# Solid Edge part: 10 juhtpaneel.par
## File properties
Author: Henri
Template: Normal.par
Last saved by: Henri
Revision: 8
Application: Solid Edge
Accuracy: 0,990
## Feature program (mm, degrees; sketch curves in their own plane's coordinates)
sketch for "unnamed Protrusion 1" plane through (0, 0, 0) normal (0, 0, 1) x-axis (1, 0, 0)
  line (-20, -175) -> (-20, 175)
  line (-20, 175) -> (20, 175)
  line (20, 175) -> (20, -175)
  line (20, -175) -> (-20, -175)
extrude "unnamed Protrusion 1" add finite 40 along +normal
sketch for "ExtrudedProtrusion_2" plane through (0, 0, 0) normal (0, 0, 1) x-axis (1, 0, 0)
  line (-95, 62.5) -> (-20, 62.5)
  line (-20, 62.5) -> (-20, 112.5)
  line (-20, 112.5) -> (-95, 112.5)
  line (-95, 112.5) -> (-95, 62.5)
extrude "ExtrudedProtrusion_2" add finite 2.5 along +normal
sketch for "ExtrudedProtrusion_3" plane through (0, 0, 0) normal (0, 0, 1) x-axis (1, 0, 0)
  line (-35, 77.5) -> (-15, 77.5)
  line (-15, 97.5) -> (-15, 77.5)
  line (-35, 97.5) -> (-15, 97.5)
  line (-35, 97.5) -> (-35, 77.5)
extrude "ExtrudedProtrusion_3" add finite 60 along +normal
sketch for "ExtrudedProtrusion_4" plane through (-35, 87.5, 31.25) normal (-1, 0, 0) x-axis (0, -1, 0)
  circle centre (0, 21.25) radius 2.5
extrude "ExtrudedProtrusion_4" add finite 7.5 along +normal
sketch for "unnamed RevolvedProtrusion 1" plane through (-27.5, 87.5, 52.5) normal (0, 0, 1) x-axis (1, 0, 0)
  line (-14.5, 24) -> (-14.5, 18.25)
  line (-15, 17.75) -> (-14.5, 18.25)
  line (-15, 17.75) -> (-15, 14.75)
  line (-15, 14.75) -> (-14.5, 13.5427)
  line (-14.5, 13.5427) -> (-14.5, 0)
  line (-13.75, 0) -> (-14.5, 0)
  line (-13.75, 26.25) -> (-13.75, 0)
revolve "unnamed RevolvedProtrusion 1" add finite 360 deg
sketch for "unnamed RevolvedProtrusion 2" plane through (-27.5, 87.5, 52.5) normal (0, 0, 1) x-axis (1, 0, 0)
  circle centre (-13.75, 16.25) radius 1
revolve "unnamed RevolvedProtrusion 2" add finite 360 deg
pattern "Pattern_1" of "unnamed RevolvedProtrusion 1" along a curve  XDirCount = 9; XDirSpacing = 50 mm
revolve "unnamed RevolvedProtrusion 3" add finite 360 deg
revolve "unnamed RevolvedProtrusion 4" add finite 360 deg
revolve "unnamed RevolvedProtrusion 5" add finite 360 deg
revolve "unnamed RevolvedProtrusion 6" add finite 360 deg
revolve "unnamed RevolvedProtrusion 7" add finite 360 deg
revolve "unnamed RevolvedProtrusion 8" add finite 360 deg
revolve "unnamed RevolvedProtrusion 9" add finite 360 deg
revolve "unnamed RevolvedProtrusion 10" add finite 360 deg
fillet "Round_1" radius 1.5
sketch used by "ExtrudedProtrusion_6" plane through (0.75, 0, 40) normal (0, 0, 1) x-axis (0, 1, 0)
extrude "ExtrudedProtrusion_6" add finite 7.5 along +normal
sketch used by "unnamed Cutout 1" plane through (-0.6086, 106.7159, 43.75) normal (0.371391, -0.928477, 0) x-axis (0.928477, 0.371391, 0)
extrude "unnamed Cutout 1" cut through along -normal
sketch used by "unnamed Cutout 2" plane through (-8.0348, 49.7139, 43.75) normal (-0.371391, -0.928477, 0) x-axis (0.928477, -0.371391, 0)
extrude "unnamed Cutout 2" cut through along -normal
sketch for "unnamed Cutout 3" plane through (-4.3225, 116.0007, 44.7494) normal (-0.319569, -0.127827, 0.938901) x-axis (0.871748, 0.348699, 0.344186)
extrude "unnamed Cutout 3" cut finite 0.5 along -normal
sketch for "ExtrudedProtrusion_7" #1 plane through (-4.3225, 116.0007, 44.7494) normal (-0.319569, -0.127827, 0.938901) x-axis (0.871748, 0.348699, 0.344186)
  line (-6.7381, 8.75) -> (6.7381, 8.75)
  line (6.7381, 8.75) -> (6.7381, -8.75)
  line (-6.7381, -8.75) -> (6.7381, -8.75)
  line (-6.7381, 8.75) -> (-6.7381, -8.75)
sketch for "ExtrudedProtrusion_7" #2 plane through (-4.3225, 116.0007, 44.7494) normal (-0.319569, -0.127827, 0.938901) x-axis (0.871748, 0.348699, 0.344186)
sketch for "ExtrudedProtrusion_7" #3 plane through (-4.3225, 116.0007, 44.7494) normal (-0.319569, -0.127827, 0.938901) x-axis (0.871748, 0.348699, 0.344186)
  circle centre (-7.4881, 7.6034) radius 0.25
sketch for "ExtrudedProtrusion_7" #4 plane through (-4.3225, 116.0007, 44.7494) normal (-0.319569, -0.127827, 0.938901) x-axis (0.871748, 0.348699, 0.344186)
  circle centre (-7.4881, 6.7282) radius 0.25
sketch for "ExtrudedProtrusion_7" #5 plane through (-4.3225, 116.0007, 44.7494) normal (-0.319569, -0.127827, 0.938901) x-axis (0.871748, 0.348699, 0.344186)
  circle centre (-7.4881, 5.9624) radius 0.25
sketch for "ExtrudedProtrusion_7" #6 plane through (-4.3225, 116.0007, 44.7494) normal (-0.319569, -0.127827, 0.938901) x-axis (0.871748, 0.348699, 0.344186)
  circle centre (-7.4881, 4.4308) radius 0.25
sketch for "ExtrudedProtrusion_7" #7 plane through (-4.3225, 116.0007, 44.7494) normal (-0.319569, -0.127827, 0.938901) x-axis (0.871748, 0.348699, 0.344186)
  circle centre (-7.4881, 3.7014) radius 0.25
extrude "ExtrudedProtrusion_7" add finite 0.5 along +normal
fillet "Round_2" radius 0.2
sketch for "ExtrudedCutout_4" plane through (-4.3209, 58.9987, 44.75) normal (-0.319565, 0.127826, 0.938903) x-axis (0.871749, -0.3487, 0.344182)
extrude "ExtrudedCutout_4" cut finite 0.5 along -normal
sketch for "ExtrudedProtrusion_8" #1 plane through (-4.3209, 58.9987, 44.75) normal (-0.319565, 0.127826, 0.938903) x-axis (0.871749, -0.3487, 0.344182)
sketch for "ExtrudedProtrusion_8" #2 plane through (-4.3209, 58.9987, 44.75) normal (-0.319565, 0.127826, 0.938903) x-axis (0.871749, -0.3487, 0.344182)
  circle centre (-7.3671, -2.1335) radius 0.25
sketch for "ExtrudedProtrusion_8" #3 plane through (-4.3209, 58.9987, 44.75) normal (-0.319565, 0.127826, 0.938903) x-axis (0.871749, -0.3487, 0.344182)
  circle centre (-7.3671, -1.3677) radius 0.25
sketch for "ExtrudedProtrusion_8" #4 plane through (-4.3209, 58.9987, 44.75) normal (-0.319565, 0.127826, 0.938903) x-axis (0.871749, -0.3487, 0.344182)
  circle centre (-7.3671, 7.203) radius 0.25
extrude "ExtrudedProtrusion_8" add finite 0.5 along +normal
fillet "Round_3" radius 0.2
sketch used by "ExtrudedProtrusion_9" plane through (0, 87.5, 0) normal (0, -1, 0) x-axis (1, 0, 0)
  line (-57.5, 37.5) -> (-73.3744, 37.5)
  line (-55, 35) -> (-55, 30)
  line (-85, 27.5) -> (-57.5, 27.5)
  arc centre (-85, 32.5) radius 5 from (-90, 32.5) to (-85, 27.5) ccw
  arc centre (-57.5, 35) radius 2.5 from (-57.5, 37.5) to (-55, 35) cw
  arc centre (-57.5, 30) radius 2.5 from (-57.5, 27.5) to (-55, 30) ccw
  line (-90, 32.5) -> (-99.1666, 68.1143)
  line (-96.7455, 71.2375) -> (-91.5997, 71.2375)
  line (-89.3147, 69.7516) -> (-75.6595, 38.9858)
  arc centre (-96.7455, 68.7375) radius 2.5 from (-99.1666, 68.1143) to (-96.7455, 71.2375) cw
  arc centre (-91.5997, 68.7375) radius 2.5 from (-91.5997, 71.2375) to (-89.3147, 69.7516) cw
  arc centre (-73.3744, 40) radius 2.5 from (-75.6595, 38.9858) to (-73.3744, 37.5) ccw
extrude "ExtrudedProtrusion_9" add finite 35 symmetric
sketch for "unnamed Protrusion 2" plane through (0, 87.5, 0) normal (0, -1, 0) x-axis (1, 0, 0)
  line (-48.5, 12.5) -> (-35, 12.5)
  line (-35, 12.5) -> (-35, 7.5)
  line (-35, 7.5) -> (-48.5, 7.5)
  arc centre (-48.5, 9) radius 1.5 from (-50, 9) to (-48.5, 7.5) ccw
  line (-50, 11) -> (-50, 9)
  arc centre (-48.5, 11) radius 1.5 from (-50, 11) to (-48.5, 12.5) cw
extrude "unnamed Protrusion 2" add finite 30 symmetric
sketch for "unnamed RevolvedProtrusion 11" plane through (0, 87.5, 0) normal (0, -1, 0) x-axis (1, 0, 0)
revolve "unnamed RevolvedProtrusion 11" add finite 360 deg
fillet "Round_6" radius 2
sketch for "ExtrudedCutout_7" plane through (0, 87.5, 0) normal (0, -1, 0) x-axis (1, 0, 0)
  line (-89.3147, 69.7516) -> (-75.6595, 38.9858)
  arc centre (-73.3744, 40) radius 2.5 from (-75.6595, 38.9858) to (-73.3744, 37.5) ccw
  line (-73.3744, 37.5) -> (-57.5, 37.5)
  line (-57.5, 37.5) -> (-73.3744, 35)
  arc centre (-73.3744, 40) radius 5 from (-77.9445, 37.9716) to (-73.3744, 35) ccw
  line (-92.7093, 71.2375) -> (-77.9445, 37.9716)
  line (-92.7093, 71.2375) -> (-91.5997, 71.2375)
  arc centre (-91.5997, 68.7375) radius 2.5 from (-91.5997, 71.2375) to (-89.3147, 69.7516) cw
extrude "ExtrudedCutout_7" cut finite 25 symmetric
fillet "Round_7" radius 2.5
fillet "Round_8" radius 1
fillet "Round_10" radius 2
sketch for "unnamed Cutout 4" plane through (0.75, 0, 40) normal (0, 0, 1) x-axis (0, 1, 0)
  line (-175, -19.25) -> (0, -19.25)
  line (0, 21.0459) -> (0, -19.25)
  line (-175, 21.0459) -> (0, 21.0459)
  line (-175, 21.0459) -> (-175, -19.25)
extrude "unnamed Cutout 4" cut through along -normal
sketch for "ExtrudedProtrusion_13" plane through (0, 87.5, 0) normal (0, -1, 0) x-axis (1, 0, 0)
  line (-33.5, 60) -> (-16.5, 60)
  line (-33.5, 70) -> (-16.5, 60)
  line (-33.5, 70) -> (-33.5, 60)
extrude "ExtrudedProtrusion_13" add finite 17 symmetric
sketch for "ExtrudedCutout_10" plane through (-33.5, 87.5, 65) normal (-1, 0, 0) x-axis (0, -1, 0)
  line (7.75, 4.25) -> (-7.75, 4.25)
  line (-7.75, -4.25) -> (-7.75, 4.25)
  line (7.75, -4.25) -> (-7.75, -4.25)
  line (7.75, 4.25) -> (7.75, -4.25)
extrude "ExtrudedCutout_10" cut finite 0.25 along -normal
fillet "Round_11" radius 0.25
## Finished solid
Body 1: solid body, 275 faces, 506 edges, 230 vertices.
  Faces by surface: cylinder 113, plane 79, torus 35, sphere 24, cone 20, blend 4
  Edges by curve: line 232, circle 197, intersection 39, ellipse 38
Bounding box of the edges (mm; curved faces can reach further): 119.246 x 175.000 x 76.266, from (-99.2455, 0, 0) to (20, 175, 76.2657).
Cylindrical faces by radius (mm): R0.2 x8, R0.25 x16, R0.75 x18, R1 x7, R1.25 x9, R1.5 x19, R2 x11, R2.5 x22, R5 x2, R10 x1
Conical faces (half-angle, radius in mm at the cone's reference point): 22.4965 deg R1.25 x9, 45 deg R0.75 x9, 45 deg R2.5 x1, 45 deg R7.5 x1
Toroidal faces (ring radius, tube radius in mm): R0.05 r0.2 x11, R1.5 r1 x2, R2.5 r2.5 x2, R3 r1.5 x6, R3.5 r1 x2, R5 r2.5 x2, R8.5 r1.5 x1, R16.25 r1 x9
Spherical faces by radius (mm): R0.25 x2, R1.25 x9, R1.5 x4, R2.5 x8, R3.75 x1
Planar faces by outward normal: +x 5, +y 8, +z 8, -x 9, -y 8, -z 4, oblique 37
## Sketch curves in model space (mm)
line (-33.5, 79.75, 69.25) -> (-33.5, 95.25, 69.25)
line (-33.5, 79.75, 69.25) -> (-33.5, 79.75, 60.75)
line (-33.5, 79.75, 60.75) -> (-33.5, 95.25, 60.75)
line (-33.5, 95.25, 60.75) -> (-33.5, 95.25, 69.25)
line (20, -175, 40) -> (20, 0, 40)
line (-20.2959, -175, 40) -> (20, -175, 40)
line (-20.2959, -175, 40) -> (-20.2959, 0, 40)
line (-20.2959, 0, 40) -> (20, 0, 40)
arc centre (-73.3744, 87.5, 40) radius 5 from (-77.9445, 87.5, 37.9716) through (-76.1, 87.5, 35.8082) to (-73.3744, 87.5, 35)
line (-57.5, 87.5, 37.5) -> (-73.3744, 87.5, 35)
line (-73.3744, 87.5, 37.5) -> (-57.5, 87.5, 37.5)
arc centre (-73.3744, 87.5, 40) radius 2.5 from (-75.6595, 87.5, 38.9858) through (-74.7372, 87.5, 37.9041) to (-73.3744, 87.5, 37.5)
line (-89.3147, 87.5, 69.7516) -> (-75.6595, 87.5, 38.9858)
arc centre (-91.5997, 87.5, 68.7375) radius 2.5 from (-91.5997, 87.5, 71.2375) through (-90.2369, 87.5, 70.8333) to (-89.3147, 87.5, 69.7516)
line (-92.7093, 87.5, 71.2375) -> (-91.5997, 87.5, 71.2375)
line (-92.7093, 87.5, 71.2375) -> (-77.9445, 87.5, 37.9716)
circle centre (-44, 87.5, 52.5) radius 16.25
arc centre (-73.3744, 87.5, 40) radius 2.5 from (-75.6595, 87.5, 38.9858) through (-74.7372, 87.5, 37.9041) to (-73.3744, 87.5, 37.5)
line (-89.3147, 87.5, 69.7516) -> (-75.6595, 87.5, 38.9858)
arc centre (-91.5997, 87.5, 68.7375) radius 2.5 from (-91.5997, 87.5, 71.2375) through (-90.2369, 87.5, 70.8333) to (-89.3147, 87.5, 69.7516)
line (-96.7455, 87.5, 71.2375) -> (-91.5997, 87.5, 71.2375)
arc centre (-96.7455, 87.5, 68.7375) radius 2.5 from (-99.1666, 87.5, 68.1143) through (-98.6755, 87.5, 70.3266) to (-96.7455, 87.5, 71.2375)
line (-90, 87.5, 32.5) -> (-99.1666, 87.5, 68.1143)
arc centre (-85, 87.5, 32.5) radius 5 from (-90, 87.5, 32.5) through (-88.4312, 87.5, 28.8631) to (-85, 87.5, 27.5)
line (-85, 87.5, 27.5) -> (-57.5, 87.5, 27.5)
arc centre (-57.5, 87.5, 30) radius 2.5 from (-57.5, 87.5, 27.5) through (-55.6816, 87.5, 28.2844) to (-55, 87.5, 30)
line (-55, 87.5, 35) -> (-55, 87.5, 30)
arc centre (-57.5, 87.5, 35) radius 2.5 from (-57.5, 87.5, 37.5) through (-55.6816, 87.5, 36.7156) to (-55, 87.5, 35)
line (-57.5, 87.5, 37.5) -> (-73.3744, 87.5, 37.5)
circle centre (-41.25, 103.75, 52.5) radius 1
line (-42.4017, 87.5, 52.5) -> (-39.1797, 87.5, 52.5)
line (-7.5722, 103.9305, 47.5) -> (6.3581, 109.5026, 47.5)
line (-7.5722, 103.9305, 47.5) -> (-7.5722, 103.9305, 42)
line (-7.5722, 103.9305, 42) -> (6.3581, 109.5026, 47.5)
line (-15, 52.5, 42) -> (-1.0695, 46.9278, 47.5)
line (-15, 52.5, 47.5) -> (-15, 52.5, 42)
line (-15, 52.5, 47.5) -> (-1.0695, 46.9278, 47.5)
arc centre (-48.5, 87.5, 9) radius 1.5 from (-50, 87.5, 9) through (-49.5294, 87.5, 7.9089) to (-48.5, 87.5, 7.5)
line (-50, 87.5, 11) -> (-50, 87.5, 9)
arc centre (-48.5, 87.5, 11) radius 1.5 from (-50, 87.5, 11) through (-49.5294, 87.5, 12.0911) to (-48.5, 87.5, 12.5)
line (-48.5, 87.5, 12.5) -> (-35, 87.5, 12.5)
line (-35, 87.5, 12.5) -> (-35, 87.5, 7.5)
line (-35, 87.5, 7.5) -> (-48.5, 87.5, 7.5)
arc centre (-75, 87.5, 17.5) radius 3.75 from (-77.5, 87.5, 14.7049) through (-78.7484, 87.5, 17.6087) to (-77.5, 87.5, 20.2951)
arc centre (-75, 87.5, 17.5) radius 3.75 from (-77.5, 87.5, 14.7049) through (-78.7484, 87.5, 17.6087) to (-77.5, 87.5, 20.2951)
line (-77.5, 87.5, 12.5) -> (-77.5, 87.5, 14.7049)
line (-77.5, 87.5, 12.5) -> (-82.5, 87.5, 7.5)
line (-83.5, 87.5, 7.5) -> (-82.5, 87.5, 7.5)
arc centre (-83.5, 87.5, 6) radius 1.5 from (-85, 87.5, 6) through (-84.5294, 87.5, 7.0911) to (-83.5, 87.5, 7.5)
line (-85, 87.5, 2.5) -> (-85, 87.5, 6)
line (-75, 87.5, 2.5) -> (-85, 87.5, 2.5)
line (-77.5, 87.5, 20.2951) -> (-77.5, 87.5, 22.5)
line (-82.5, 87.5, 27.5) -> (-77.5, 87.5, 22.5)
line (-75, 87.5, 27.5) -> (-82.5, 87.5, 27.5)
line (-75, 87.5, 27.5) -> (-75, 87.5, 2.5)
circle centre (-11.954, 116.1491, 42.1721) radius 0.25
circle centre (-12.2249, 116.8263, 42.1721) radius 0.25
circle centre (-12.4958, 117.5035, 42.1721) radius 0.25
circle centre (-13.0646, 118.9255, 42.1721) radius 0.25
circle centre (-13.349, 119.6366, 42.1721) radius 0.25
circle centre (-13.9449, 121.1264, 42.1721) radius 0.25
circle centre (-13.6741, 120.4492, 42.1721) radius 0.25
line (-6.9467, 105.5269, 42.4302) -> (4.801, 110.226, 47.0685)
line (-1.6983, 126.4744, 47.0685) -> (4.801, 110.226, 47.0685)
line (-13.4461, 121.7753, 42.4302) -> (-1.6983, 126.4744, 47.0685)
line (-13.4461, 121.7753, 42.4302) -> (-6.9467, 105.5269, 42.4302)
circle centre (-11.5355, 59.5866, 42.2144) radius 0.25
circle centre (-11.251, 60.2977, 42.2144) radius 0.25
circle centre (-8.068, 68.2553, 42.2144) radius 0.25
circle centre (-7.7294, 69.1019, 42.2144) radius 0.25
line (4.8044, 64.7726, 47.0698) -> (-1.695, 48.5243, 47.0698)
line (-1.695, 48.5243, 47.0698) -> (-13.4461, 53.2247, 42.4302)
line (-6.9467, 69.4731, 42.4302) -> (-13.4461, 53.2247, 42.4302)
line (-6.9467, 69.4731, 42.4302) -> (4.8044, 64.7726, 47.0698)
line (-33.5, 87.5, 60) -> (-16.5, 87.5, 60)
line (-33.5, 87.5, 70) -> (-16.5, 87.5, 60)
line (-33.5, 87.5, 70) -> (-33.5, 87.5, 60)
line (-42.5, 105.25, 52.5) -> (-42, 105.75, 52.5)
line (-42.5, 105.25, 52.5) -> (-42.5, 102.25, 52.5)
line (-42.5, 102.25, 52.5) -> (-42, 101.0427, 52.5)
line (-42, 101.0427, 52.5) -> (-42, 87.5, 52.5)
line (-41.25, 87.5, 52.5) -> (-42, 87.5, 52.5)
line (-41.25, 113.75, 52.5) -> (-41.25, 87.5, 52.5)
arc centre (-41.25, 112.5, 52.5) radius 1.25 from (-42, 111.5, 52.5) through (-42.4359, 112.8953, 52.5) to (-41.25, 113.75, 52.5)
line (-42, 111.5, 52.5) -> (-42, 105.75, 52.5)
circle centre (-42.5, 87.5, 52.5) radius 16.25
line (-35, 87.5, 52.5) -> (-45, 87.5, 52.5)
circle centre (-35, 87.5, 52.5) radius 2.5
line (-35, 87.5, 64.2069) -> (-35, 87.5, 43.5789)
line (-35, 69.5584, 52.5) -> (-35, 104.2903, 52.5)
line (-23.8304, 122.5, 40) -> (26.1084, 122.5, 40)
line (-25.2462, 52.5, 40) -> (23.9204, 52.5, 40)
line (-10, 97.5, 40) -> (8.218, 97.5, 40)
line (-10, 77.5, 40) -> (3.8419, 77.5, 40)
line (-14.5634, 62.5, 40) -> (8.3467, 62.5, 40)
line (-13.405, 112.5, 40) -> (13.6237, 112.5, 40)
line (-10, 58.4341, 40) -> (-10, 115.8381, 40)
line (-5, 41.5733, 40) -> (-5, 127.4218, 40)
line (-15, 48.6523, 40) -> (-15, 126.2635, 40)
line (-32.5, 95, 40) -> (-17.5, 95, 40)
line (-17.5, 95, 40) -> (-17.5, 80, 40)
line (-17.5, 80, 40) -> (-32.5, 80, 40)
line (-32.5, 80, 40) -> (-32.5, 95, 40)
line (-7.5722, 71.0695, 40) -> (6.3583, 65.4973, 40)
line (6.3583, 65.4973, 40) -> (-1.0695, 46.9278, 40)
line (-1.0695, 46.9278, 40) -> (-15, 52.5, 40)
line (-15, 52.5, 40) -> (-7.5722, 71.0695, 40)
line (-7.5722, 103.9305, 40) -> (6.355, 109.5013, 40)
line (6.355, 109.5013, 40) -> (-1.0728, 128.0709, 40)
line (-1.0728, 128.0709, 40) -> (-15, 122.5, 40)
line (-15, 122.5, 40) -> (-7.5722, 103.9305, 40)
line (-10.7842, 99.1914, 0) -> (-10.7842, 73.4747, 0)
line (-129.3743, 87.5, 0) -> (-45.0579, 87.5, 0)
line (-15, 97.5, 0) -> (-15, 77.5, 0)
line (-35, 77.5, 0) -> (-15, 77.5, 0)
line (-35, 97.5, 0) -> (-35, 77.5, 0)
line (-35, 97.5, 0) -> (-15, 97.5, 0)
line (-95, 112.5, 0) -> (-95, 62.5, 0)
line (-95, 62.5, 0) -> (-20, 62.5, 0)
line (-20, 62.5, 0) -> (-20, 112.5, 0)
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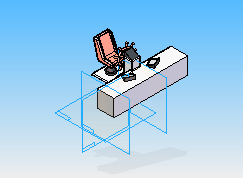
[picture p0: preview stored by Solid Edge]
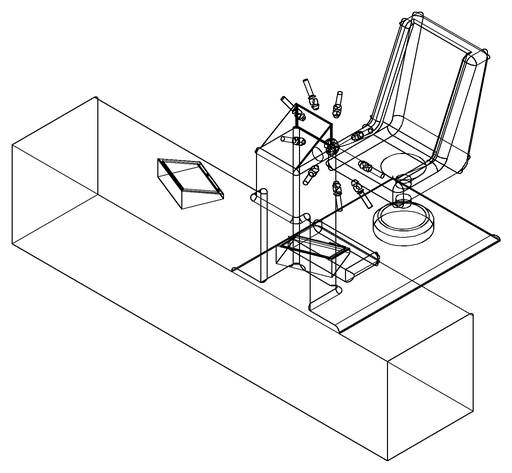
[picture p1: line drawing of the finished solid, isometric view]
